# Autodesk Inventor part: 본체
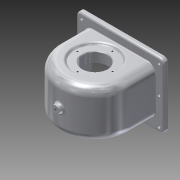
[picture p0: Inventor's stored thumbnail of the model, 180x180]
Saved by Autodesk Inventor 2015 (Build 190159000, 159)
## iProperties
Created: 2015-09
Part Number: 본체
Material: 알루미늄 6061
Document SubType Name: Modeling
Designer: Administrator
Density: 2.7 g/cm^3
Appearance: 알루미늄 - 평지
Mass: 680.655 g
Surface Area: 892.914 cm^2
Volume: 252.095 cm^3
Author: Administrator
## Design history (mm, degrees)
sketch "스케치1"
  geometry: L1 (63, 52)-(-63, 52); L2 (-70, 45)-(-70, -45); L3 (-63, -52)-(63, -52); L4 (70, -45)-(70, 45); A1 r 7 centre (63, 45) between (70, 45) and (63, 52); A2 r 7 centre (-63, 45) between (-63, 52) and (-70, 45); A3 r 7 centre (-63, -45) between (-70, -45) and (-63, -52); A4 r 7 centre (63, -45) between (63, -52) and (70, -45); 5 further points
  constraints: 8 end point, 8 point on circle, 8 tangent, 6 point on line, 4 centre point, 3 equal radius, 2 parallel, 1 horizontal, 1 perpendicular
  dimensions: "d0" = 104 distance of point (70, -52) point (70, 52); "d1" = 140 distance of point (70, 52) point (-70, 52); "d2" = 7 radius of A1
extrude "돌출1" new body sketch "스케치1" distance "d3" = 7; taper "d4" = 0 deg
sketch "스케치2"
  geometry: 1 further point
sketch "스케치13"
  geometry: L1 (63, 52)-(-63, 52) reference; L2 (70, -45)-(70, 45) reference; L3 (-63, -52)-(63, -52) reference; L4 (62, 52)-(62, 44); L5 (62, 44)-(62, 0); L6 (62, 0)-(62, -44); L7 (0, 52)-(0, -52); C1 r 2.5 at (62, 44); C2 r 2.5 at (62, 0); C3 r 2.5 at (62, -44); C4 r 2.5 at (-62, 44); C5 r 2.5 at (-62, 0); C6 r 2.5 at (-62, -44); 1 further point
  constraints: 8 end point, 6 centre point, 3 coincident, 3 symmetric about line, 2 midpoint, 2 point on line, 2 vertical, 3 other
  dimensions: "d30" = 8 distance of L4.start L4.end; "d31" = 5 diameter of C1; "d32" = 44 distance of L5.start L5.end; "d33" = 44 distance of L5.end L6.end; "d34" = 5 diameter of C2; "d35" = 5 diameter of C3
extrude "돌출8" cut sketch "스케치13" stored distance "d36" = 7; taper "d37" = 0 deg
sketch "스케치15"
  geometry: L1 (-63, 7)-(63, 7) reference; L2 (0, 7)-(0, -97); L3 (0, 7)-(0, -40); L4 (-57, -40)-(-57, 0); L5 (57, -40)-(57, 0); L6 (-57, 0)-(57, 0); L7 (63, 0)-(-63, 0) reference; A1 r 57 centre (0, -40) between (-57, -40) and (57, -40); 1 further point
  constraints: 10 end point, 3 point on circle, 3 vertical, 1 centre point, 1 coincident, 1 collinear, 1 midpoint, 1 point on line, 1 tangent
  dimensions: "d40" = 104 distance of L2.start L2.end; "d41" = 47 distance of L2.start L3.end
extrude "돌출9" join sketch "스케치15" stored distance "d42" = 77; taper "d43" = 0 deg
sketch "스케치16"
  geometry: 1 further point
feature "쉘2" dims "d46" = 5
sketch "스케치17"
  geometry: L1 (120.126, 84.126)-(120.126, 53.874) reference; L2 (107.126, 80.5)-(3.126, 80.5) reference; L3 (107.126, 13.5)-(107.126, 80.5) reference; L4 (3.126, 13.5)-(107.126, 13.5) reference; L5 (3.126, 80.5)-(3.126, 13.5) reference; L6 (-9.874, 53.874)-(-9.874, 84.126) reference; L7 (-9.874, 9.874)-(-9.874, 40.126) reference; L8 (110.252, 0)-(0, 0) reference; L9 (120.126, 40.126)-(120.126, 9.874) reference; L10 (120.126, 84.126)-(120.126, 53.874) reference; L11 (0, 94)-(110.252, 94) reference; A1 r 7.5 centre (-6.874, 91) between (-9.874, 84.126) and (0, 94) reference; A2 r 7.5 centre (-6.874, 47) between (-9.874, 40.126) and (-9.874, 53.874) reference; A3 r 7.5 centre (-6.874, 3) between (0, 0) and (-9.874, 9.874) reference; A4 r 7.5 centre (117.126, 3) between (120.126, 9.874) and (110.252, 0) reference; A5 r 7.5 centre (117.126, 47) between (120.126, 53.874) and (120.126, 40.126) reference; A6 r 7.5 centre (117.126, 91) between (110.252, 94) and (120.126, 84.126) reference; 1 further point
extrude "돌출11" join sketch "스케치17" stored distance "d47" = 5; taper "d48" = 0 deg
node "작업 평면2"
sketch "스케치18"
  geometry: C1 r 6 at (0, 0); 1 further point
  constraints: 1 centre point, 1 coincident
  dimensions: "d50" = 12 diameter of C1
extrude "돌출12" join sketch "스케치18" distance "d51" = 8; taper "d52" = 10 deg
sketch "스케치19"
  geometry: L1 (-63, 7)-(63, 7) reference; L2 (0, 7)-(0, -40); C1 r 31 at (0, -40); 1 further point
  constraints: 2 end point, 1 centre point, 1 coincident, 1 midpoint, 1 vertical
  dimensions: "d53" = 47 distance of L2.start L2.end; "d54" = 62 diameter of C1
extrude "돌출13" join sketch "스케치19" distance "d55" = 10; taper "d56" = 0 deg
sketch "스케치20"
  geometry: C1 r 20 at (0, 0); 1 further point
  constraints: 1 centre point
  dimensions: "d57" = 40 diameter of C1
extrude "돌출14" cut sketch "스케치20" stored distance "d58" = 10; taper "d59" = 0 deg
sketch "스케치22"
  geometry: L1 (-40, 38.5)-(-97, 38.5) reference; L2 (7, 2.5)-(7, -2.5) reference; L3 (7, 0)-(-40, 0); L4 (-40, 33.5)-(-40, 19.5); L5 (-68, 19.5)-(-40, 19.5); L6 (-68, 19.5)-(-79.747, 33.5); L7 (-40, 19.5)-(-40, 33.5); L8 (-40, 33.5)-(-92, 33.5) reference; L9 (-79.747, 33.5)-(-40, 33.5); 1 further point
  constraints: 12 end point, 3 point on line, 1 horizontal, 1 midpoint, 1 perpendicular
  dimensions: "d61" = 47 distance of L3.start L3.end
revolve "회전1" sketch "스케치22" stored, may be unused: angle "d67" = 90 deg
sketch "스케치23"
  geometry: L1 (-52, 7)-(52, 7) reference; L2 (0, 7)-(0, -40); C1 r 33 at (0, -40); 1 further point
  constraints: 2 end point, 1 centre point, 1 coincident, 1 midpoint, 1 vertical
  dimensions: "d68" = 47 distance of L2.start L2.end; "d69" = 66 diameter of C1
extrude "돌출15" cut sketch "스케치23" distance "d70" = 3; taper "d71" = 0 deg
sketch "스케치24"
  geometry: C1 r 20 at (0, 0); 1 further point
  constraints: 1 centre point
  dimensions: "d72" = 40 diameter of C1
extrude "돌출16" cut sketch "스케치24" distance "d73" = 16; taper "d74" = 0 deg
sketch "스케치25"
  geometry: L1 (-38.5, 47.613)-(-38.5, 17.613); 2 further points
  constraints: 2 end point, 1 vertical, 1 other
  dimensions: "d75" = 30 distance of L1.start L1.end
feature "엠보싱1" sketch "스케치25" dims "d0" = 104, "d1" = 140, "d2" = 7, "d76" = 0.5, "d77" = 0
sketch "스케치26"
  geometry: 2 further points
hole "구멍1" sketch "스케치26" at (0.204, -27.999) diameter "d79" = 2.459; stored, may be unused: countersink angle "d83" = 90 deg, drill point angle "d85" = 118 deg; dims "d80" = 7, "d81" = 4, "d82" = 2, "d84" = 9
sketch "스케치27" dims "d90" = 48
  geometry: L1 (-52, 47)-(52, 47) reference; L2 (0, 47)-(0, 0); 3 further points
  constraints: 2 end point, 1 coincident, 1 midpoint, 1 vertical, 1 vertical alignment, 2 other
  dimensions: "d89" = 47 distance of L2.start L2.end
hole "구멍2" sketch "스케치27" at (0, -24) diameter "d91" = 2.459; stored, may be unused: countersink angle "d95" = 90 deg, drill point angle "d97" = 118 deg; dims "d92" = 6, "d93" = 4, "d94" = 2, "d96" = 8
hole "구멍3" diameter "d103" = 4.459; stored, may be unused: countersink angle "d107" = 90 deg, drill point angle "d109" = 118 deg; dims "d101" = 10, "d102" = 10, "d104" = 20, "d105" = 4, "d106" = 2, "d108" = 20
fillet "모깎기1" dims "d110" = 3, "d111" = 14
fillet "모깎기2" dims "d112" = 1, "d113" = 3, "d114" = 9
chamfer "모따기1" distance "d115" = 1; stored, may be unused: second distance "d116" = 2, angle "d117" = 45 deg
chamfer "모따기2" distance "d118" = 1; stored, may be unused: second distance "d119" = 2, angle "d120" = 45 deg
fillet "모깎기3" dims "d121" = 3
chamfer "모따기3" distance "d122" = 1; stored, may be unused: second distance "d123" = 2, angle "d124" = 45 deg
node "솔리드1"
pattern_circular "원형 패턴1" dims angle "d87" = 360 deg
pattern_circular "원형 패턴2" dims angle "d99" = 360 deg
node "투영된 루프1"
